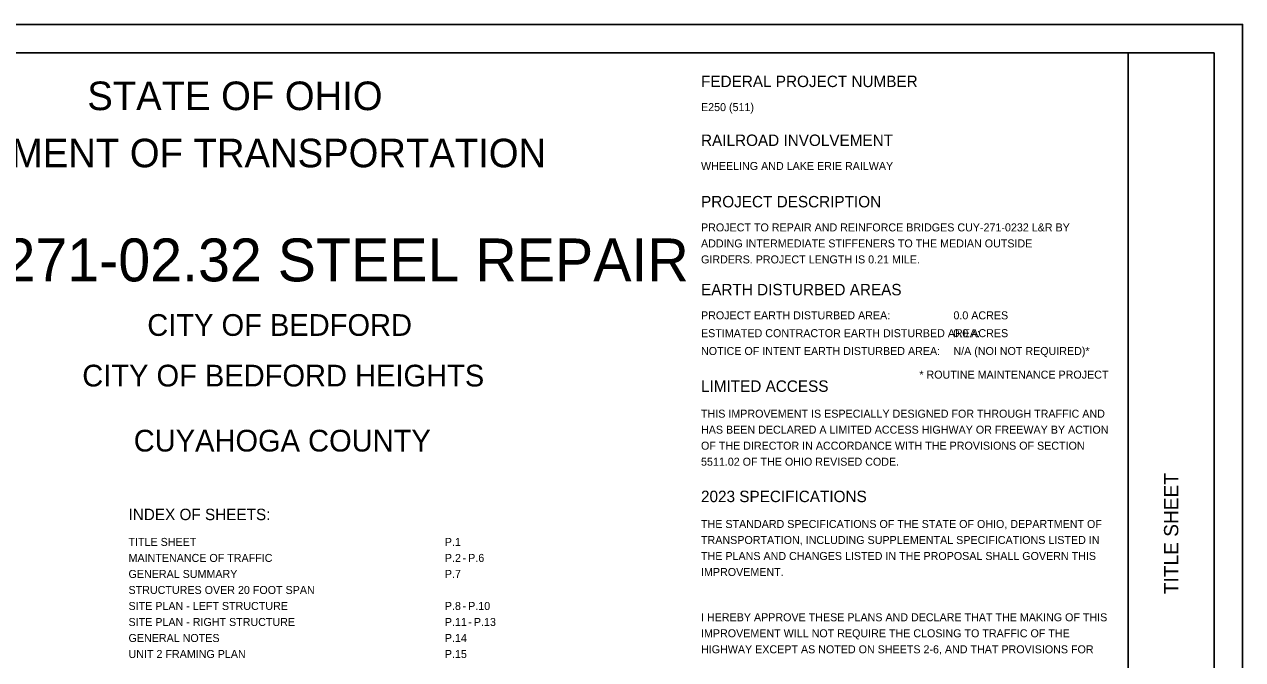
# Model space of a CAD drawing. Extents: x 0 to 34, y 0 to 22.
# Drawn here: x 12.69 to 34, y 10.89 to 22 of the extents above; entities that cross this region are included whole.
import ezdxf

# ---------------------------------------------------------------- set-up
doc = ezdxf.new("R2010")
doc.units = 0
for name, color, linetype in [('SH_Border', 7, 'Continuous'), ('SH_Cut_Line', 7, 'Continuous'), ('SH_Data', 7, 'Continuous'), ('SH_Text', 7, 'Continuous')]:
    doc.layers.add(name, color=color, linetype=linetype)

msp = doc.modelspace()

# ---------------------------------------------------------------- linework, layer by layer
at = {"layer": 'SH_Border'}
msp.add_line((32, 0.5), (32, 21.5), dxfattribs=at)
msp.add_lwpolyline([(1.5, 21.5), (33.5, 21.5), (33.5, 0.5), (1.5, 0.5)], close=True, dxfattribs=at)
at = {"layer": 'SH_Cut_Line'}
msp.add_lwpolyline([(0, 0), (34, 0), (34, 22), (0, 22)], close=True, dxfattribs=at)
at = {"layer": 'SH_Data'}
msp.add_line((24.528, 15.261), (24.528, 15.261), dxfattribs=at)

# ---------------------------------------------------------------- texts
msp.add_text('TITLE SHEET', height=0.25, rotation=90, dxfattribs=at).set_placement((32.875, 12.035))
at = {"layer": 'SH_Text'}
for s, height, p in [('FEDERAL PROJECT NUMBER', 0.2, (24.528, 20.903)), ('STATE OF OHIO', 0.5, (13.795, 20.5)), ('E250 (511)', 0.14, (24.528, 20.483)), ('RAILROAD INVOLVEMENT', 0.2, (24.528, 19.873)), ('DEPARTMENT OF TRANSPORTATION', 0.5, (9.747, 19.5)), ('WHEELING AND LAKE ERIE RAILWAY', 0.14, (24.528, 19.453)), ('PROJECT DESCRIPTION', 0.2, (24.528, 18.799)), ('PROJECT TO REPAIR AND REINFORCE BRIDGES CUY-271-0232 L&R BY ', 0.14, (24.528, 18.379)), ('CUY-271-02.32 STEEL REPAIR', 0.75, (9.878, 17.505)), ('ADDING INTERMEDIATE STIFFENERS TO THE MEDIAN OUTSIDE ', 0.14, (24.528, 18.099)), ('GIRDERS. PROJECT LENGTH IS 0.21 MILE.', 0.14, (24.528, 17.819)), ('EARTH DISTURBED AREAS', 0.2, (24.528, 17.261)), ('CITY OF BEDFORD', 0.38, (14.844, 16.552)), ('PROJECT EARTH DISTURBED AREA:', 0.14, (24.528, 16.841)), ('0.0 ACRES', 0.14, (28.942, 16.841)), ('ESTIMATED CONTRACTOR EARTH DISTURBED AREA:', 0.14, (24.528, 16.529)), ('0.0 ACRES', 0.14, (28.942, 16.529)), ('NOTICE OF INTENT EARTH DISTURBED AREA:', 0.14, (24.528, 16.217)), ('N/A (NOI NOT REQUIRED)*', 0.14, (28.942, 16.217)), ('CITY OF BEDFORD HEIGHTS', 0.38, (13.707, 15.667)), ('LIMITED ACCESS', 0.2, (24.528, 15.573)), ('* ROUTINE MAINTENANCE PROJECT', 0.14, (28.346, 15.804)), ('THIS IMPROVEMENT IS ESPECIALLY DESIGNED FOR THROUGH TRAFFIC AND', 0.14, (24.528, 15.121)), ('CUYAHOGA COUNTY', 0.38, (14.607, 14.529)), ('HAS BEEN DECLARED A LIMITED ACCESS HIGHWAY OR FREEWAY BY ACTION', 0.14, (24.528, 14.841)), ('OF THE DIRECTOR IN ACCORDANCE WITH THE PROVISIONS OF SECTION', 0.14, (24.528, 14.561)), ('5511.02 OF THE OHIO REVISED CODE.', 0.14, (24.528, 14.281)), ('2023 SPECIFICATIONS', 0.2, (24.528, 13.644)), ('INDEX OF SHEETS:', 0.2, (14.516, 13.329)), ('THE STANDARD SPECIFICATIONS OF THE STATE OF OHIO, DEPARTMENT OF', 0.14, (24.528, 13.192)), ('TITLE SHEET', 0.14, (14.516, 12.878)), ('P.1', 0.14, (20.048, 12.878)), ('TRANSPORTATION, INCLUDING SUPPLEMENTAL SPECIFICATIONS LISTED IN', 0.14, (24.528, 12.912)), ('MAINTENANCE OF TRAFFIC', 0.14, (14.516, 12.598)), ('P.2', 0.14, (20.048, 12.598)), ('-', 0.14, (20.357, 12.598)), ('P.6', 0.14, (20.456, 12.598)), ('THE PLANS AND CHANGES LISTED IN THE PROPOSAL SHALL GOVERN THIS', 0.14, (24.528, 12.632)), ('GENERAL SUMMARY', 0.14, (14.516, 12.318)), ('P.7', 0.14, (20.048, 12.318)), ('IMPROVEMENT.', 0.14, (24.528, 12.352)), ('STRUCTURES OVER 20 FOOT SPAN', 0.14, (14.516, 12.038)), ('SITE PLAN - LEFT STRUCTURE', 0.14, (14.516, 11.758)), ('P.8', 0.14, (20.048, 11.758)), ('-', 0.14, (20.357, 11.758)), ('P.10', 0.14, (20.456, 11.758)), ('SITE PLAN - RIGHT STRUCTURE', 0.14, (14.516, 11.478)), ('P.11', 0.14, (20.048, 11.478)), ('-', 0.14, (20.458, 11.478)), ('P.13', 0.14, (20.556, 11.478)), ('I HEREBY APPROVE THESE PLANS AND DECLARE THAT THE MAKING OF THIS', 0.14, (24.528, 11.56)), ('GENERAL NOTES', 0.14, (14.516, 11.198)), ('P.14', 0.14, (20.048, 11.198)), ('IMPROVEMENT WILL NOT REQUIRE THE CLOSING TO TRAFFIC OF THE ', 0.14, (24.528, 11.28)), ('HIGHWAY EXCEPT AS NOTED ON SHEETS 2-6, AND THAT PROVISIONS FOR ', 0.14, (24.528, 11)), ('UNIT 2 FRAMING PLAN', 0.14, (14.516, 10.918)), ('P.15', 0.14, (20.048, 10.918))]:
    msp.add_text(s, height=height, dxfattribs=at).set_placement(p)

doc.saveas('drawing.dxf')
